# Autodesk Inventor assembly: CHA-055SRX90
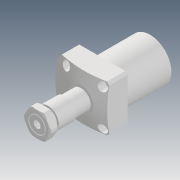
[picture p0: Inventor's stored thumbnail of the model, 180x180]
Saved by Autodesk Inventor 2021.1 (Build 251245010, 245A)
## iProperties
Created: 2019-05
Part Number: CHA-055SRX90
Description: STEP AP203
Document SubType Name: Assembly
Designer: user
Title: CHA-055SRX90.STEP
Revision Number: ÈÎºÎ
Sending System: SolidWorks 2017
Preprocessor: SwSTEP 2.0
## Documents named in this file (5)
- D:\Vault_2016\Projekty\Clamptek\Hydraulic\CHA\CHA\CHA-055\Inventor\CHA-055SRX90\CHA-055SRX90.iam
- D:\Vault_2016\Projekty\Clamptek\Hydraulic\CHA\CHA\CHA-055\Inventor\CHA-055SRX90\CHA-055±¾Ìå.ipt
- D:\Vault_2016\Projekty\Clamptek\Hydraulic\CHA\CHA\CHA-055\Inventor\CHA-055SRX90\CHA-055»îÈû¸Ë.ipt
- D:\Vault_2016\Projekty\Clamptek\Hydraulic\CHA\CHA\CHA-055\Inventor\CHA-055SRX90\CHA-055S×¶Ì×.ipt
- D:\Vault_2016\Projekty\Clamptek\Hydraulic\CHA\CHA\CHA-055\Inventor\CHA-055SRX90\CHA-055ÂÝÄ¸.ipt
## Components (4 placed, 4 different names)
1. CHA-055±¾Ìå_1
2. CHA-055»îÈû¸Ë_2
3. CHA-055S×¶Ì×_3
4. CHA-055ÂÝÄ¸_4
